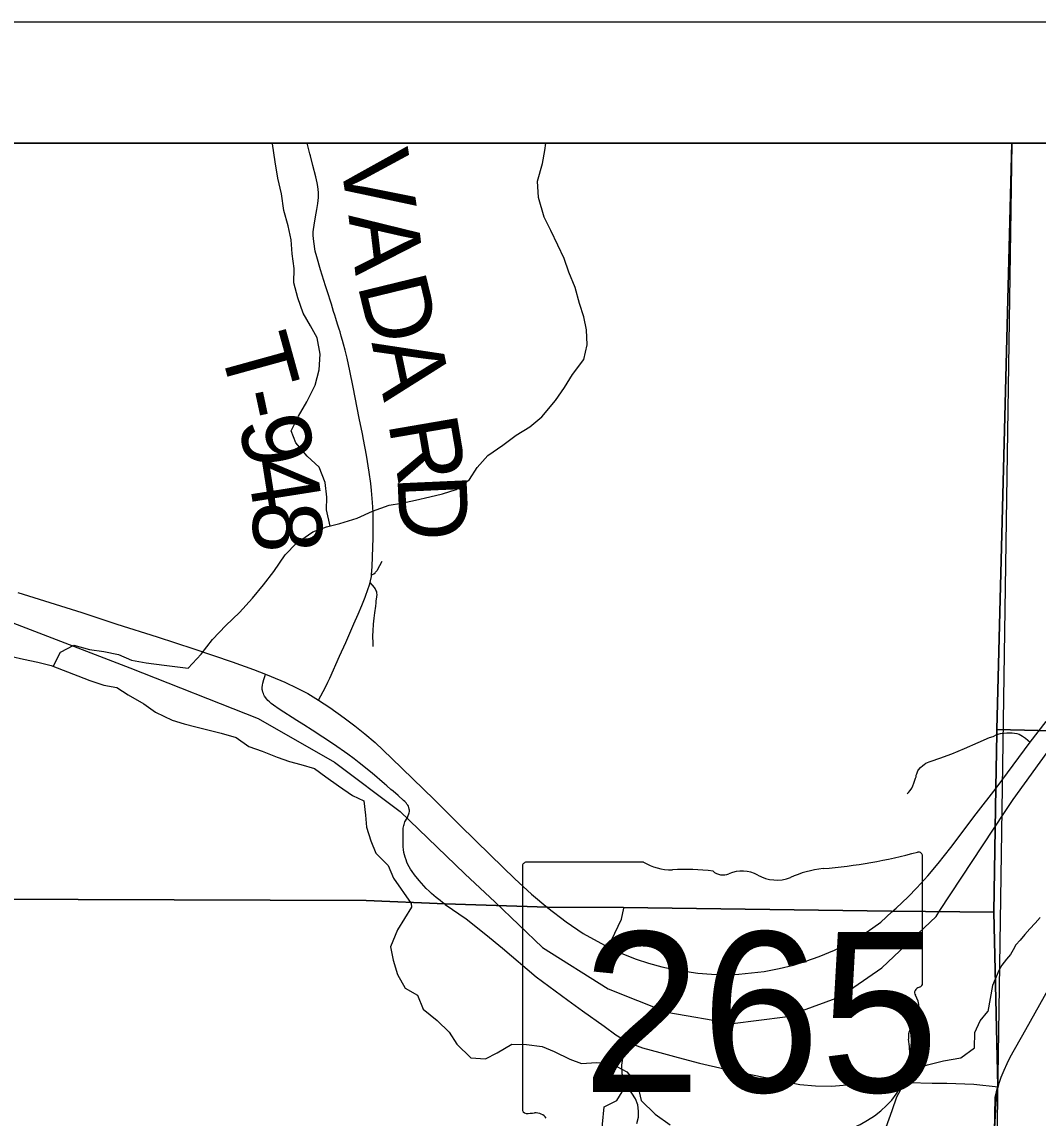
# Model space of a CAD drawing. Extents: x 0 to 34, y 0 to 22.
# Drawn here: x 26.286 to 27.124, y 20.097 to 21 of the extents above; entities that cross this region are included whole.
import ezdxf

# ---------------------------------------------------------------- set-up
doc = ezdxf.new("R2010")
doc.units = 0
for name, color, linetype in [('GM_X_Corporation', 7, 'Continuous'), ('GM_X_County', 7, 'Continuous'), ('GM_X_Minor_River', 7, 'Continuous'), ('GM_X_Rail_Line', 7, 'Continuous'), ('GM_X_State_Location', 7, 'Continuous'), ('GM_X_State_Route', 7, 'Continuous'), ('GM_X_State_Shield', 7, 'Continuous'), ('GM_X_Township_Road', 7, 'Continuous'), ('GM_X_Township_Road_Text', 7, 'Continuous'), ('SH_Data', 7, 'Continuous')]:
    doc.layers.add(name, color=color, linetype=linetype)

msp = doc.modelspace()

# ---------------------------------------------------------------- linework, layer by layer
at = {"layer": 'GM_X_Corporation'}
for points in [[(27.1022, 20.9), (23.51667, 20.9), (23.51667, 20.32759), (24.03282, 20.3169), (24.06884, 20.31647), (24.52494, 20.31067), (25.45068, 20.29493), (26.25334, 20.27732), (26.57015, 20.27599), (26.63511, 20.27345), (26.71959, 20.27068), (26.78221, 20.2704), (27.00306, 20.26728), (27.08729, 20.26647), (27.08896, 20.36917), (27.08968, 20.41348), (27.08976, 20.41697)], [(27.1022, 20.9), (23.51667, 20.9), (23.51667, 20.32759), (24.03282, 20.3169), (24.06884, 20.31647), (24.52494, 20.31067), (25.45068, 20.29493), (26.25334, 20.27732), (26.57015, 20.27599), (26.63511, 20.27345), (26.71959, 20.27068), (26.78221, 20.2704), (27.00306, 20.26728), (27.08729, 20.26647), (27.08896, 20.36917), (27.08968, 20.41348), (27.08976, 20.41697)], [(30.31667, 20.36493), (30.31667, 20.9), (27.1022, 20.9), (27.08976, 20.41697), (27.12389, 20.41631), (27.2336, 20.4152), (27.58291, 20.41163), (27.67509, 20.4106), (29.55027, 20.37882)]]:
    msp.add_lwpolyline(points, close=True, dxfattribs=at)
for points in [[(30.31667, 20.9), (27.1022, 20.9), (27.08976, 20.41697), (27.08968, 20.41348), (27.08896, 20.36917), (27.08729, 20.26647), (27.09073, 20.12299), (27.08852, 20.11389), (27.08642, 20.01381), (27.07613, 19.68064), (27.07326, 19.49798), (27.07194, 19.39116), (27.04874, 18.58046), (27.04191, 17.82361), (27.03491, 17.55216), (27.02338, 16.66109), (27.01239, 14.98802), (27.00568, 14.51357), (27.29989, 14.51067), (27.80309, 14.50906), (28.4032, 14.497)], [(29.55027, 20.37882), (27.67509, 20.4106), (27.58291, 20.41163), (27.2336, 20.4152), (27.12389, 20.41631), (27.08976, 20.41697), (27.08968, 20.41348), (27.08896, 20.36917), (27.08729, 20.26647), (27.09073, 20.12299), (27.08852, 20.11389), (27.08642, 20.01381), (27.07613, 19.68064), (27.07326, 19.49798), (27.07194, 19.39116), (27.04874, 18.58046), (27.04191, 17.82361), (27.03491, 17.55216), (27.02338, 16.66109), (27.01239, 14.98802), (27.00568, 14.51357), (27.29989, 14.51067), (27.80309, 14.50906), (28.4032, 14.497)], [(27.02338, 16.66109), (27.03491, 17.55216), (27.04191, 17.82361), (27.04874, 18.58046), (27.07194, 19.39116), (27.07326, 19.49798), (27.07613, 19.68064), (27.08642, 20.01381), (27.08852, 20.11389), (27.09073, 20.12299), (27.08729, 20.26647), (27.00306, 20.26728), (26.78221, 20.2704), (26.71959, 20.27068), (26.63511, 20.27345), (26.57015, 20.27599), (26.25334, 20.27732), (25.45068, 20.29493), (24.52494, 20.31067), (24.06884, 20.31647), (24.03282, 20.3169), (23.51667, 20.32759), (23.51667, 14.56416)], [(27.02338, 16.66109), (27.03491, 17.55216), (27.04191, 17.82361), (27.04874, 18.58046), (27.07194, 19.39116), (27.07326, 19.49798), (27.07613, 19.68064), (27.08642, 20.01381), (27.08852, 20.11389), (27.09073, 20.12299), (27.08729, 20.26647), (27.00306, 20.26728), (26.78221, 20.2704), (26.71959, 20.27068), (26.63511, 20.27345), (26.57015, 20.27599), (26.25334, 20.27732), (25.45068, 20.29493), (24.52494, 20.31067), (24.06884, 20.31647), (24.03282, 20.3169), (23.51667, 20.32759), (23.51667, 14.56416)]]:
    msp.add_lwpolyline(points, dxfattribs=at)
at = {"layer": 'GM_X_County'}
msp.add_line((27.1022, 20.9), (27.00568, 14.51357), dxfattribs=at)
at = {"layer": 'GM_X_Minor_River'}
for points in [[(26.31227, 20.46899), (26.31834, 20.48073), (26.32923, 20.48659), (26.34214, 20.483), (26.35389, 20.4813), (26.36604, 20.47884), (26.3767, 20.47408), (26.38883, 20.472), (26.40362, 20.46997), (26.42333, 20.46763), (26.43413, 20.47917), (26.44341, 20.49106), (26.45459, 20.50261), (26.46578, 20.51339), (26.47658, 20.52531), (26.4855, 20.53606), (26.49404, 20.54719), (26.50329, 20.56097), (26.51261, 20.57059), (26.5261, 20.5799), (26.53739, 20.58387), (26.54832, 20.5867), (26.56263, 20.59109), (26.5754, 20.59698), (26.58895, 20.60174), (26.59914, 20.60342), (26.61083, 20.60588), (26.62252, 20.60872), (26.63308, 20.61116), (26.64438, 20.61475), (26.65523, 20.62288), (26.66151, 20.63283), (26.67044, 20.64282), (26.6828, 20.65135), (26.69366, 20.65948), (26.7049, 20.66648), (26.715, 20.6746), (26.72615, 20.68803), (26.73356, 20.69876), (26.74021, 20.70947), (26.74949, 20.72175), (26.75234, 20.73391), (26.75178, 20.74641), (26.74936, 20.75697), (26.74579, 20.7679), (26.7422, 20.78111), (26.73709, 20.7939), (26.73314, 20.80521), (26.72806, 20.81611), (26.72222, 20.82814), (26.71676, 20.83904), (26.71199, 20.85525), (26.71141, 20.86888), (26.71536, 20.88334), (26.71747, 20.89398), (26.71804, 20.9)], [(26.54038, 20.58464), (26.53756, 20.59789), (26.53778, 20.6085), (26.53647, 20.62061), (26.53137, 20.63303), (26.5214, 20.64234), (26.51216, 20.65318), (26.50823, 20.66297), (26.51449, 20.67519), (26.52112, 20.68704), (26.52811, 20.70079), (26.53133, 20.71334), (26.53228, 20.72624), (26.52981, 20.73984), (26.52437, 20.7496), (26.51817, 20.76011), (26.51382, 20.77254), (26.51061, 20.78499), (26.51082, 20.79674), (26.50913, 20.80883), (26.5082, 20.82056), (26.50577, 20.83189), (26.50218, 20.84471), (26.50047, 20.85832), (26.49725, 20.87115), (26.49516, 20.88475), (26.49306, 20.89949), (26.49295, 20.9)], [(26.2783, 20.47706), (26.28778, 20.47494), (26.29955, 20.47247), (26.31056, 20.46962), (26.32045, 20.46599), (26.33262, 20.46125), (26.34252, 20.45725), (26.35392, 20.45364), (26.36455, 20.45153), (26.37409, 20.44562), (26.38706, 20.43825), (26.39662, 20.43121), (26.41034, 20.42461), (26.42021, 20.42173), (26.42971, 20.41923), (26.44072, 20.41637), (26.4506, 20.41388), (26.46313, 20.41029), (26.47345, 20.40288), (26.48448, 20.39926), (26.49666, 20.39415), (26.50693, 20.39053), (26.51642, 20.38803), (26.52744, 20.38479), (26.537, 20.37812), (26.54732, 20.37071), (26.55879, 20.36256), (26.56831, 20.35816), (26.56962, 20.34643), (26.57052, 20.3366), (26.57409, 20.32529), (26.57802, 20.31512), (26.58838, 20.30505), (26.5927, 20.29451), (26.60712, 20.27374), (26.60753, 20.27056)], [(26.60753, 20.27056), (26.59593, 20.25204), (26.59006, 20.23793), (26.59246, 20.22697), (26.59601, 20.21525), (26.6022, 20.20395), (26.61249, 20.19801), (26.61717, 20.18669), (26.62864, 20.17735), (26.63859, 20.16762), (26.64477, 20.15783), (26.65625, 20.1466), (26.66837, 20.14561), (26.67814, 20.15067), (26.69016, 20.15764), (26.70226, 20.15742), (26.71515, 20.15568), (26.72503, 20.15163), (26.73797, 20.14535), (26.74747, 20.14167), (26.75994, 20.14259), (26.77243, 20.14161), (26.785, 20.13494), (26.79383, 20.12443), (26.79665, 20.11118), (26.80813, 20.09995), (26.82072, 20.09138)], [(27.12539, 20.26197), (27.12131, 20.25735), (27.11685, 20.25272), (27.11277, 20.2481), (27.10907, 20.24348), (27.10535, 20.23962), (27.10316, 20.23541), (27.10095, 20.23158), (27.09761, 20.22773), (27.09392, 20.22273), (27.09134, 20.21852), (27.08628, 20.20615), (27.08248, 20.18456)], [(27.00022, 20.06735), (26.99905, 20.07731), (26.99852, 20.08944), (27.00364, 20.10316), (27.00729, 20.11421), (27.01394, 20.12643), (27.01987, 20.13636), (27.03267, 20.1407), (27.04587, 20.1439), (27.06021, 20.14635), (27.07145, 20.15484), (27.07168, 20.16736), (27.0761, 20.17689), (27.08248, 20.18456)]]:
    msp.add_lwpolyline(points, dxfattribs=at)
at = {"layer": 'GM_X_Rail_Line'}
msp.add_line((27.04294, 20.26779), (27.09617, 20.34866), dxfattribs=at)
for points in [[(25.84274, 20.9), (25.89507, 20.85127), (25.94516, 20.79237), (25.98459, 20.73941), (26.04434, 20.67165), (26.079, 20.62847), (26.1292, 20.58125), (26.16984, 20.5536), (26.20957, 20.53181), (26.26099, 20.51185), (26.37549, 20.46794), (26.48103, 20.42595), (26.54398, 20.39009), (26.59807, 20.34936), (26.65153, 20.29821), (26.67649, 20.27462)], [(27.09617, 20.34866), (27.10321, 20.35936), (27.15695, 20.43382), (27.23063, 20.51302), (27.40626, 20.69391), (27.58107, 20.88831), (27.59007, 20.9)], [(26.67649, 20.27462), (26.71547, 20.23733), (26.76961, 20.20329), (26.81786, 20.18401), (26.87194, 20.17485), (26.91531, 20.18022), (26.96039, 20.19681), (26.99509, 20.22071), (27.03969, 20.26285), (27.04294, 20.26779)]]:
    msp.add_lwpolyline(points, dxfattribs=at)
at = {"layer": 'GM_X_State_Route'}
for points in [[(26.28312, 20.5299), (26.33587, 20.51333), (26.36481, 20.50388), (26.39796, 20.49332), (26.42804, 20.48339), (26.45983, 20.47271), (26.47736, 20.46643), (26.48727, 20.46256), (26.4918, 20.46079), (26.5032, 20.45595), (26.51327, 20.45119), (26.52201, 20.44656), (26.53088, 20.44123), (26.54031, 20.43501), (26.55191, 20.42672), (26.56084, 20.42004), (26.56904, 20.41345), (26.57746, 20.40616), (26.59106, 20.39346), (26.62621, 20.35927), (26.64734, 20.33825), (26.67256, 20.31339), (26.69269, 20.29399), (26.70647, 20.28141), (26.71979, 20.27014)], [(27.08916, 20.36864), (27.10781, 20.39383), (27.11722, 20.40659), (27.13029, 20.42355)], [(27.0915, 20.12452), (27.09179, 20.12556), (27.09344, 20.1305), (27.09585, 20.13638), (27.09826, 20.14187), (27.10076, 20.14697), (27.11368, 20.16992), (27.13686, 20.21109), (27.14967, 20.2342), (27.16661, 20.26404), (27.17961, 20.28754), (27.19059, 20.30612), (27.20002, 20.32162), (27.20628, 20.33231), (27.21177, 20.34242), (27.21571, 20.35079), (27.21909, 20.35859), (27.22217, 20.36706), (27.22515, 20.37611), (27.22794, 20.38593), (27.23006, 20.39488), (27.2317, 20.40297), (27.23304, 20.41154), (27.2342, 20.42271)], [(27.00326, 20.26675), (27.00676, 20.26988), (27.01678, 20.27925), (27.02375, 20.28641), (27.03297, 20.29656), (27.04146, 20.30654), (27.05193, 20.31971), (27.07287, 20.34759), (27.08916, 20.36864)], [(26.71979, 20.27014), (26.73485, 20.25865), (26.74903, 20.24891), (26.76966, 20.23769), (26.77707, 20.23399), (26.78363, 20.23124), (26.79263, 20.22764), (26.80289, 20.22447), (26.81379, 20.2214), (26.82533, 20.21897), (26.84331, 20.21632), (26.85474, 20.21537), (26.86681, 20.21505), (26.87728, 20.21537), (26.88755, 20.21643), (26.89802, 20.2177), (26.9103, 20.22002), (26.92226, 20.22288), (26.93236, 20.22621), (26.94342, 20.22997), (26.95591, 20.23526), (26.96543, 20.24002), (26.97516, 20.24563), (26.98299, 20.25039), (26.99411, 20.25812), (27.00326, 20.26675)], [(27.08812, 20.08834), (27.08863, 20.09866), (27.0893, 20.10913), (27.08995, 20.11627), (27.09094, 20.12246), (27.0915, 20.12452)]]:
    msp.add_lwpolyline(points, dxfattribs=at)
at = {"layer": 'GM_X_State_Shield'}
for p, q in [((27.02854, 20.20801), (27.02854, 20.31269)), ((26.69896, 20.30429), (26.69896, 20.10417)), ((26.79872, 20.30773), (26.7022, 20.30773)), ((27.02851, 20.20803), (27.02854, 20.20801))]:
    msp.add_line(p, q, dxfattribs=at)
for centre, major_axis, start_param, end_param in [((26.91114, 20.58057), (0.34952, 0), 4.814394, 5.042369), ((27.02488, 20.31313), (0.00367, 0), 6.141152, 7.989035), ((26.70273, 20.30472), (0.00382, 0), 1.712693, 3.28349), ((26.82171, 20.33097), (0.03703, 0), 4.042523, 4.731795), ((26.83399, 20.19538), (0.13295, 0), 1.404758, 1.657858), ((26.86417, 20.30575), (0.01068, 0), 3.836095, 5.185415), ((26.87985, 20.28262), (0.02221, 0), 0.950623, 2.079405), ((26.90853, 20.31435), (0.02672, 0), 4.081561, 5.145723), ((26.95572, 20.24661), (0.07032, 0), 1.699011, 2.107814), ((27.02769, 20.20032), (0.00568, 0), 1.883978, 3.671073), ((27.02462, 20.2076), (0.00393, 0), 5.05454, 6.418171), ((26.99157, 20.18709), (0.03409, 0), 5.934695, 6.695948), ((27.04168, 20.1642), (0.0248, 0), 2.387724, 3.262537), ((26.93072, 20.15088), (0.08742, 0), 5.101752, 6.440018), ((26.70277, 20.10373), (0.00385, 0), 3.00124, 4.508301), ((26.70335, 20.12421), (0.0294, 0), 4.665946, 4.897461), ((26.70936, 20.09262), (0.0106, 0), 0.519207, 1.627899)]:
    msp.add_ellipse(centre, major_axis=major_axis, ratio=0.8, start_param=start_param, end_param=end_param, dxfattribs=at)
at = {"layer": 'GM_X_Township_Road'}
for points in [[(26.5745, 20.54435), (26.57506, 20.55121), (26.57539, 20.55927), (26.57577, 20.5748), (26.57595, 20.58537), (26.57585, 20.59591), (26.5757, 20.60023), (26.57548, 20.60395), (26.5746, 20.61379), (26.57388, 20.61979), (26.5726, 20.62893), (26.57038, 20.64302), (26.56805, 20.65585), (26.56709, 20.66072), (26.56439, 20.67349), (26.56264, 20.68201), (26.55939, 20.6991), (26.55671, 20.7125), (26.55457, 20.72284), (26.55295, 20.72941), (26.55143, 20.73457), (26.55068, 20.7375), (26.5496, 20.74099), (26.54862, 20.74453), (26.54787, 20.74685), (26.54668, 20.75027), (26.54557, 20.75377), (26.54508, 20.75555), (26.54425, 20.7585), (26.54331, 20.76142), (26.54241, 20.76436), (26.54153, 20.76732), (26.53806, 20.77857), (26.53667, 20.78266), (26.53254, 20.79567), (26.52935, 20.80635), (26.52816, 20.81114), (26.52697, 20.81907), (26.52658, 20.824), (26.52657, 20.82709), (26.52749, 20.83448), (26.52894, 20.84241), (26.52956, 20.84543), (26.53037, 20.8503), (26.53081, 20.85523), (26.53082, 20.85956), (26.5303, 20.86447), (26.52978, 20.86747), (26.52873, 20.87224), (26.52624, 20.8818), (26.52418, 20.88958), (26.52378, 20.89139), (26.52274, 20.89558), (26.52165, 20.9)], [(26.5745, 20.54435), (26.57537, 20.54467), (26.57637, 20.54519), (26.57741, 20.54603), (26.57793, 20.54652), (26.57849, 20.54714), (26.57906, 20.54787), (26.57958, 20.54867), (26.58325, 20.5558)], [(26.53088, 20.44123), (26.53464, 20.44819), (26.5358, 20.45033), (26.53855, 20.45588), (26.54012, 20.45925), (26.54828, 20.4774), (26.55327, 20.48879), (26.55985, 20.50406), (26.56353, 20.51196), (26.56657, 20.5192), (26.56929, 20.52602), (26.57187, 20.53328), (26.57266, 20.5355), (26.57338, 20.5381)], [(26.57338, 20.5381), (26.57378, 20.53952), (26.5744, 20.54316), (26.5745, 20.54435)], [(26.57601, 20.4855), (26.57594, 20.48639), (26.57586, 20.48798), (26.57574, 20.49415), (26.57576, 20.49843), (26.57617, 20.5039), (26.57672, 20.50882), (26.57728, 20.51313), (26.57798, 20.51857), (26.57841, 20.52149), (26.5785, 20.52268), (26.5789, 20.52629), (26.57906, 20.5282), (26.57902, 20.52943), (26.57888, 20.53027), (26.57862, 20.53106), (26.57821, 20.53193), (26.57781, 20.53268), (26.57744, 20.53324), (26.577, 20.53388), (26.57338, 20.5381)], [(26.51889, 20.42075), (26.51302, 20.42447), (26.49832, 20.43378), (26.49374, 20.437), (26.49194, 20.43845), (26.49041, 20.43978), (26.48923, 20.44093), (26.48828, 20.44203), (26.48649, 20.44456), (26.48588, 20.44569), (26.4854, 20.44676), (26.48495, 20.44789), (26.48468, 20.44907), (26.48457, 20.44989), (26.48454, 20.45149), (26.48478, 20.45358), (26.48508, 20.45529), (26.48589, 20.45822), (26.4869, 20.46141), (26.48727, 20.46256)], [(26.63532, 20.27291), (26.63305, 20.27459), (26.63117, 20.27599), (26.62793, 20.27854), (26.62582, 20.28022), (26.62406, 20.28183), (26.62196, 20.28372), (26.61966, 20.28604), (26.61382, 20.29247), (26.60989, 20.29727), (26.60798, 20.29991), (26.60671, 20.30185), (26.60552, 20.30382), (26.60457, 20.30571), (26.60367, 20.30772), (26.60295, 20.30967), (26.60227, 20.31179), (26.60171, 20.31383), (26.6012, 20.31573), (26.60079, 20.31816), (26.60059, 20.32043), (26.60048, 20.32304), (26.60048, 20.3305), (26.6005, 20.33207), (26.6005, 20.33365), (26.60056, 20.33469), (26.60064, 20.33576), (26.60081, 20.33683), (26.60104, 20.33785), (26.60133, 20.33876), (26.60174, 20.33991), (26.6021, 20.34081), (26.60256, 20.34184), (26.60407, 20.34459), (26.60448, 20.34536), (26.60484, 20.34614), (26.60534, 20.3474), (26.6056, 20.34837), (26.60573, 20.34932), (26.60576, 20.35043), (26.60564, 20.35146), (26.60532, 20.35261), (26.6049, 20.35371), (26.60434, 20.35464), (26.60371, 20.35556), (26.60299, 20.3565), (26.60204, 20.35756), (26.60099, 20.35861), (26.59652, 20.36258), (26.59236, 20.36608), (26.59045, 20.36767), (26.58718, 20.37051), (26.58532, 20.37214), (26.57494, 20.381), (26.56432, 20.38957), (26.56022, 20.39275), (26.55489, 20.39666), (26.54323, 20.40489), (26.5256, 20.41649), (26.51889, 20.42075)], [(27.01592, 20.36387), (27.01694, 20.36506), (27.01843, 20.36675), (27.01986, 20.36877), (27.02065, 20.37045), (27.02149, 20.37285), (27.02228, 20.37515), (27.02285, 20.37691), (27.02323, 20.37813), (27.02344, 20.37924), (27.02379, 20.38049), (27.0241, 20.3814), (27.02438, 20.38225), (27.0248, 20.38306), (27.02527, 20.38389), (27.02685, 20.38581), (27.02873, 20.38744), (27.02994, 20.38828), (27.03132, 20.38916), (27.03261, 20.3898), (27.03412, 20.39048), (27.03565, 20.39103), (27.04291, 20.3934), (27.05282, 20.39697), (27.06309, 20.40125), (27.07435, 20.40624), (27.08382, 20.41031), (27.08669, 20.41126), (27.08988, 20.41295)], [(27.08988, 20.41295), (27.09289, 20.41362), (27.09552, 20.41403), (27.0979, 20.41423), (27.10229, 20.41416)], [(27.10229, 20.41416), (27.10432, 20.41393), (27.10622, 20.41361), (27.10809, 20.41306), (27.10942, 20.41239), (27.11087, 20.41149), (27.11326, 20.40977), (27.11722, 20.40659)], [(26.63532, 20.27291), (26.65242, 20.26087), (26.66871, 20.24796), (26.68247, 20.23695), (26.71009, 20.21315), (26.73633, 20.19399), (26.74829, 20.1851), (26.76617, 20.17251), (26.77591, 20.16553), (26.78687, 20.15876), (26.79771, 20.15463), (26.8121, 20.15082), (26.82723, 20.14669), (26.84469, 20.14214), (26.86522, 20.13727), (26.88564, 20.13294), (26.92755, 20.12458), (26.94046, 20.12331), (26.95389, 20.1232), (26.97876, 20.12532), (26.99654, 20.12648), (27.0176, 20.12627), (27.03654, 20.12563), (27.0486, 20.12563), (27.07072, 20.12468), (27.09094, 20.12246)], [(26.76966, 20.23769), (26.78046, 20.26076), (26.78241, 20.26986)], [(26.79327, 20.09232), (26.7944, 20.09764), (26.7946, 20.10245), (26.79388, 20.10777), (26.79214, 20.11269), (26.78905, 20.11747), (26.78464, 20.12413), (26.78279, 20.12733), (26.78109, 20.13315), (26.78088, 20.14045), (26.78162, 20.14627), (26.78321, 20.15188), (26.78687, 20.15876)], [(26.71101, 19.97513), (26.71934, 19.98196), (26.73388, 19.99733), (26.74058, 20.00743), (26.74687, 20.02105), (26.74976, 20.02589), (26.75904, 20.03878), (26.76574, 20.05322), (26.76709, 20.05869), (26.76451, 20.07488), (26.76482, 20.09191), (26.76636, 20.10612), (26.77657, 20.11118), (26.78464, 20.12413)]]:
    msp.add_lwpolyline(points, dxfattribs=at)
at = {"layer": 'SH_Data'}
for points in [[(23.41667, 21), (30.41667, 21), (30.41667, 14), (23.41667, 14)], [(23.51667, 20.9), (30.31667, 20.9), (30.31667, 14.1), (23.51667, 14.1)]]:
    msp.add_lwpolyline(points, close=True, dxfattribs=at)

# ---------------------------------------------------------------- texts
at = {"layer": 'GM_X_State_Location'}
for s, p in [('s', (26.86005, 20.19093)), ('r', (26.86004, 20.19093))]:
    msp.add_text(s, height=0.000189, dxfattribs=at).set_placement(p)
msp.add_text('265', height=0.000189, rotation=0.00001, dxfattribs=at).set_placement((26.79318, 20.17715))
at = {"layer": 'GM_X_State_Shield'}
msp.add_text('265', height=0.131836, dxfattribs=at).set_placement((26.74809, 20.11828))
at = {"layer": 'GM_X_Township_Road_Text'}
for s, rotation, p in [('V', 278.51186, (26.54812, 20.88978)), ('A', 276.79156, (26.55546, 20.84078)), ('D', 283.7084, (26.5627, 20.78377)), ('T', 285.45621, (26.4487, 20.73342)), ('A', 281.95509, (26.57445, 20.73564)), ('-', 282.06314, (26.45982, 20.69332)), ('9', 281.23953, (26.46465, 20.67072)), ('R', 279.7421, (26.58811, 20.67013)), ('4', 279.00375, (26.47137, 20.63697)), ('D', 272.56535, (26.59581, 20.62601)), ('8', 270.66094, (26.47666, 20.60458))]:
    msp.add_text(s, height=0.05682, rotation=rotation, dxfattribs=at).set_placement(p)

doc.saveas('drawing.dxf')
